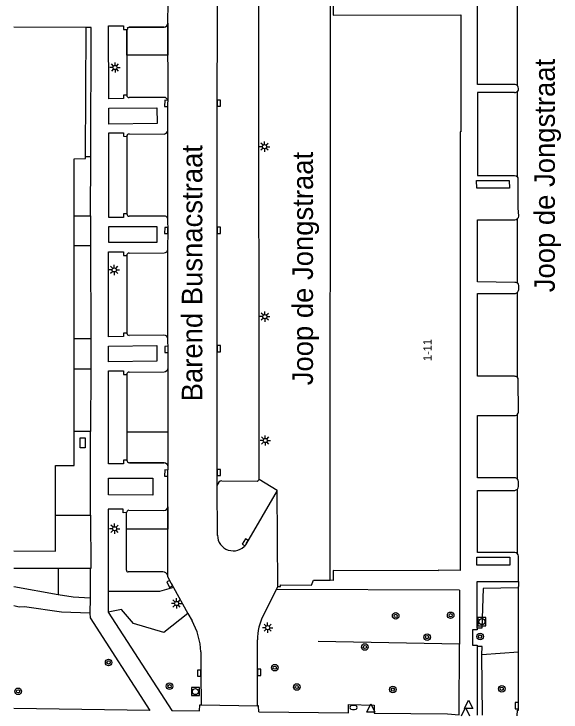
# Model space of a CAD drawing. Extents: x 132573 to 132944, y 398226 to 398676.
# Drawn here: x 132573 to 132639.7, y 398296.9 to 398381.9 of the extents above; entities that cross this region are included whole.
import ezdxf

# ---------------------------------------------------------------- set-up
doc = ezdxf.new("R2010")
doc.units = 0
for name, color, linetype in [('bp-grn-parkeervak', 7, 'Continuous'), ('gg-afsc-hekwerk', 7, 'Continuous'), ('gg-afsc-muur', 7, 'Continuous'), ('gg-anno-huisnummerreeks BGT', 7, 'Continuous'), ('gg-anno-openbare ruimte label', 7, 'Continuous'), ('gg-bbg-hoofdgebouw', 7, 'Continuous'), ('gg-knt-verharding', 7, 'Continuous'), ('gg-knt-verharding nz', 7, 'Continuous'), ('gt-grn-groengrens', 7, 'Continuous'), ('gt-grn-vlakafsluiter', 7, 'Continuous'), ('gt-symb-boom', 7, 'Continuous'), ('gt-symb-brandkraan', 7, 'Continuous'), ('gt-symb-kolk', 7, 'Continuous'), ('gt-symb-lichtmast', 7, 'Continuous'), ('gt-symb-rioolschacht', 7, 'Continuous'), ('gt-symb-waterafsluiter', 7, 'Continuous')]:
    doc.layers.add(name, color=color, linetype=linetype)

msp = doc.modelspace()

# ---------------------------------------------------------------- linework, layer by layer
at = {"layer": 'bp-grn-parkeervak'}
for p, q in [((132587.078, 398327.266), (132591.316, 398327.248)), ((132587.014, 398321.464), (132591.292, 398321.445))]:
    msp.add_line(p, q, dxfattribs=at)
for points in [[(132591.774, 398380.797), (132591.78, 398376.895), (132586.771, 398376.895), (132586.761, 398380.023)], [(132591.312, 398380.323), (132587.071, 398380.328), (132586.855, 398380.239)], [(132591.798, 398326.771), (132591.799, 398330.992), (132586.775, 398330.987), (132586.778, 398327.56)], [(132591.762, 398321.878), (132591.758, 398319.153), (132586.742, 398319.161), (132586.752, 398321.184)]]:
    msp.add_lwpolyline(points, dxfattribs=at)
for centre, radius, start, end in [((132591.29, 398380.807), 0.484, 272.60423, 358.86482), ((132586.766, 398380.149), 0.126, 267.76694, 45.19713), ((132587.103, 398327.592), 0.327, 185.59938, 265.55807), ((132591.277, 398326.727), 0.523, 4.87648, 85.72097), ((132587.037, 398321.18), 0.285, 94.57153, 179.2327), ((132591.283, 398321.926), 0.481, 271.05126, 354.25603)]:
    msp.add_arc(centre, radius, start, end, dxfattribs=at)
at = {"layer": 'gg-afsc-hekwerk'}
msp.add_line((132627.306, 398305.146), (132610.076, 398305.499), dxfattribs=at)
at = {"layer": 'gg-afsc-muur'}
for p, q in [((132582.398, 398364.533), (132581.737, 398364.536)), ((132582.362, 398357.351), (132582.398, 398364.533)), ((132580.365, 398357.35), (132582.362, 398357.351)), ((132580.363, 398353.723), (132582.357, 398353.724)), ((132582.357, 398353.724), (132582.371, 398342.349)), ((132582.371, 398342.349), (132580.355, 398342.351)), ((132580.353, 398338.703), (132582.375, 398338.705)), ((132582.375, 398338.705), (132582.362, 398331.08)), ((132582.362, 398331.08), (132580.348, 398331.081)), ((132578.093, 398320.891), (132582.363, 398320.888)), ((132578.389, 398314.392), (132573.021, 398314.394)), ((132582.303, 398314.391), (132578.389, 398314.392))]:
    msp.add_line(p, q, dxfattribs=at)
msp.add_lwpolyline([(132582.363, 398320.888), (132582.372, 398314.382), (132582.303, 398314.391)], dxfattribs=at)
at = {"layer": 'gg-bbg-hoofdgebouw'}
for p, q in [((132611.557, 398312.941), (132611.606, 398383.108)), ((132581.798, 398380.279), (132573.021, 398380.302)), ((132581.737, 398364.536), (132581.798, 398380.279)), ((132580.363, 398353.723), (132580.365, 398357.35)), ((132580.355, 398342.351), (132580.363, 398353.723)), ((132580.353, 398338.703), (132580.355, 398342.351)), ((132580.348, 398331.081), (132580.353, 398338.703))]:
    msp.add_line(p, q, dxfattribs=at)
for points in [[(132611.918, 398383.098), (132611.926, 398381.783), (132627.465, 398381.808), (132627.459, 398367.583), (132627.387, 398367.583), (132627.398, 398314.148)], [(132580.365, 398357.35), (132580.37, 398364.296), (132581.736, 398364.312), (132581.737, 398364.536)], [(132578.093, 398320.891), (132578.091, 398326.918), (132580.345, 398326.927), (132580.348, 398331.081)], [(132573.021, 398316.523), (132578.094, 398316.502), (132578.093, 398320.891)], [(132627.398, 398314.148), (132624.725, 398314.174), (132624.721, 398314.097), (132611.91, 398314.13), (132611.919, 398312.93), (132611.557, 398312.941)]]:
    msp.add_lwpolyline(points, dxfattribs=at)
at = {"layer": 'gg-knt-verharding'}
for p, q in [((132602.886, 398325.225), (132602.874, 398390.164)), ((132591.774, 398380.797), (132591.822, 398383.309)), ((132634.355, 398373.168), (132634.362, 398383.497)), ((132582.439, 398380.277), (132581.798, 398380.279)), ((132582.398, 398364.533), (132582.439, 398380.277)), ((132586.761, 398380.023), (132586.768, 398372.038)), ((132634.351, 398362.103), (132634.365, 398372.512)), ((132591.286, 398371.767), (132587.051, 398371.746)), ((132586.767, 398367.018), (132586.764, 398357.56)), ((132587.066, 398367.32), (132591.307, 398367.294)), ((132582.362, 398357.351), (132582.357, 398353.724)), ((132591.284, 398357.303), (132587.07, 398357.276)), ((132634.357, 398349.129), (132634.37, 398357.003)), ((132587.06, 398352.807), (132591.304, 398352.825)), ((132586.764, 398352.507), (132586.763, 398343.037)), ((132634.351, 398337.642), (132634.372, 398348.04)), ((132582.371, 398342.349), (132582.375, 398338.705)), ((132591.29, 398342.8), (132587.065, 398342.761)), ((132587.055, 398338.306), (132591.32, 398338.337)), ((132586.769, 398337.993), (132586.778, 398327.56)), ((132634.367, 398325.261), (132634.381, 398333.155)), ((132582.363, 398320.888), (132582.362, 398331.08)), ((132591.316, 398327.248), (132587.078, 398327.266)), ((132597.818, 398318.415), (132597.785, 398324.487)), ((132598.356, 398325.052), (132602.634, 398325.026)), ((132634.374, 398316.167), (132634.351, 398324.046)), ((132586.718, 398314.164), (132586.752, 398321.184)), ((132587.014, 398321.464), (132591.292, 398321.445)), ((132582.303, 398314.391), (132582.287, 398310.746)), ((132591.15, 398313.973), (132586.931, 398313.97)), ((132592.179, 398312.588), (132592.472, 398312.06)), ((132634.497, 398312.805), (132634.496, 398312.189)), ((132578.413, 398311.185), (132573.021, 398312.134)), ((132592.472, 398312.06), (132594.22, 398308.911)), ((132603.405, 398308.699), (132604.996, 398311.826)), ((132604.996, 398311.826), (132605.181, 398312.174)), ((132627.3, 398311.718), (132604.996, 398311.826)), ((132627.3, 398311.718), (132627.306, 398305.146)), ((132629.461, 398307.114), (132629.455, 398312.182)), ((132634.494, 398304.203), (132634.496, 398312.011)), ((132634.496, 398312.011), (132634.496, 398312.189)), ((132584.512, 398311.559), (132584.513, 398309.043)), ((132582.287, 398310.746), (132582.274, 398308.95)), ((132584.513, 398309.043), (132592.259, 398297.07)), ((132594.22, 398308.911), (132594.727, 398307.998)), ((132602.678, 398305.651), (132602.678, 398305.668)), ((132627.276, 398296.559), (132627.306, 398305.146)), ((132629.446, 398304.885), (132629.462, 398296.509)), ((132589.589, 398297.093), (132573.021, 398297.328)), ((132595.812, 398297.788), (132602.674, 398297.644)), ((132592.259, 398297.07), (132595.639, 398297.036))]:
    msp.add_line(p, q, dxfattribs=at)
for points in [[(132634.001, 398373.324), (132629.494, 398373.344), (132629.497, 398383.328), (132634.028, 398383.333), (132634.212, 398383.38), (132634.362, 398383.497)], [(132586.768, 398372.038), (132586.347, 398372.028), (132586.347, 398371.614), (132584.582, 398371.581), (132584.558, 398380.46)], [(132584.558, 398380.46), (132586.347, 398380.46), (132586.357, 398380.037), (132586.761, 398380.023)], [(132586.855, 398380.239), (132587.071, 398380.328), (132591.312, 398380.323)], [(132634.355, 398373.168), (132634.43, 398373.042), (132634.468, 398372.795), (132634.44, 398372.645), (132634.365, 398372.512)], [(132634.008, 398372.344), (132629.482, 398372.341), (132629.493, 398362.267), (132634.019, 398362.261), (132634.201, 398362.216), (132634.351, 398362.103)], [(132591.778, 398367.767), (132591.782, 398371.026), (132591.79, 398371.329)], [(132584.574, 398370.444), (132590.441, 398370.502), (132590.462, 398368.568), (132584.594, 398368.509), (132584.574, 398370.444)], [(132586.764, 398357.56), (132586.348, 398357.563), (132586.354, 398357.135), (132584.575, 398357.118), (132584.578, 398367.461), (132586.353, 398367.443), (132586.352, 398367.028), (132586.767, 398367.018)], [(132634.37, 398357.003), (132634.476, 398357.136), (132634.544, 398357.292), (132634.456, 398358.312), (132634.452, 398360.324), (132634.467, 398361.824), (132634.432, 398361.973), (132634.351, 398362.103)], [(132591.781, 398353.29), (132591.793, 398355.531), (132591.787, 398356.831)], [(132634.03, 398349.226), (132629.513, 398349.292), (132629.484, 398356.848), (132634.033, 398356.837), (132634.214, 398356.895), (132634.37, 398357.003)], [(132590.445, 398356.028), (132590.435, 398354.078), (132584.573, 398354.067), (132584.583, 398356.018), (132590.445, 398356.028)], [(132586.763, 398343.037), (132586.362, 398343.039), (132586.376, 398342.63), (132584.554, 398342.583), (132584.545, 398352.949), (132586.35, 398352.938), (132586.349, 398352.51), (132586.764, 398352.507)], [(132634.357, 398349.129), (132634.446, 398348.998), (132634.474, 398348.842), (132634.473, 398348.338), (132634.45, 398348.18), (132634.372, 398348.04)], [(132634.009, 398337.793), (132629.493, 398337.804), (132629.501, 398347.893), (132634.034, 398347.882)], [(132591.8, 398338.808), (132591.81, 398341.064), (132591.786, 398342.356)], [(132590.421, 398341.524), (132590.408, 398339.62), (132584.527, 398339.556), (132584.541, 398341.459), (132590.421, 398341.524)], [(132586.778, 398327.56), (132586.365, 398327.558), (132586.367, 398327.126), (132584.539, 398327.117), (132584.549, 398338.436), (132586.355, 398338.469), (132586.369, 398338.012), (132586.769, 398337.993)], [(132634.381, 398333.155), (132634.452, 398333.285), (132634.475, 398333.431), (132634.469, 398337.353), (132634.436, 398337.508), (132634.351, 398337.642)], [(132634.022, 398325.413), (132629.508, 398325.43), (132629.509, 398332.995), (132634.039, 398332.993)], [(132591.762, 398321.878), (132591.773, 398325.987), (132591.798, 398326.771)], [(132589.947, 398323.316), (132584.523, 398323.337), (132584.534, 398325.389), (132589.959, 398325.368), (132589.947, 398323.316)], [(132634.351, 398324.046), (132634.44, 398324.186), (132634.477, 398324.348), (132634.475, 398324.966), (132634.448, 398325.124), (132634.367, 398325.261)], [(132605.083, 398323.893), (132601.371, 398317.481), (132601.259, 398317.265)], [(132634.374, 398316.167), (132634.222, 398316.286), (132634.035, 398316.336), (132629.51, 398316.335), (132629.511, 398323.887), (132634.027, 398323.893), (132634.204, 398323.938), (132634.351, 398324.046)], [(132586.752, 398321.184), (132586.34, 398321.163), (132586.339, 398321.598), (132584.508, 398321.613), (132584.512, 398311.559)], [(132634.497, 398312.805), (132634.486, 398315.885), (132634.453, 398316.035), (132634.374, 398316.167)], [(132592.179, 398312.588), (132591.756, 398313.368), (132591.749, 398313.466)], [(132629.455, 398312.182), (132629.455, 398312.807), (132634.497, 398312.805)], [(132582.287, 398310.746), (132580.232, 398310.865), (132578.413, 398311.185)], [(132582.274, 398308.95), (132578.802, 398309.064), (132574.303, 398309.686), (132573.669, 398309.674), (132573.021, 398309.813)], [(132582.274, 398308.95), (132582.294, 398308.375), (132589.589, 398297.093)], [(132629.461, 398307.114), (132629.462, 398306.896), (132628.872, 398306.896), (132628.87, 398305.054), (132629.446, 398305.036), (132629.446, 398304.885)], [(132602.674, 398297.644), (132602.696, 398301.73), (132602.678, 398305.651)], [(132595.804, 398304.223), (132595.796, 398301.617), (132595.812, 398297.788)], [(132634.339, 398296.427), (132634.357, 398297.106), (132634.5, 398297.123), (132634.494, 398304.203)], [(132595.639, 398297.036), (132595.656, 398297.769), (132595.812, 398297.788)], [(132602.844, 398296.935), (132602.819, 398297.628), (132602.674, 398297.644)], [(132602.844, 398296.935), (132613.776, 398296.784), (132613.762, 398297.795), (132616.926, 398297.724), (132616.905, 398296.758), (132625.831, 398296.661), (132627.276, 398296.559)]]:
    msp.add_lwpolyline(points, dxfattribs=at)
for centre, radius, start, end in [((132591.29, 398380.807), 0.484, 272.60423, 358.86482), ((132586.766, 398380.149), 0.126, 267.76694, 45.19713), ((132634.019, 398372.884), 0.44, 40.14956, 92.28638), ((132634.008, 398372.808), 0.464, 270.01582, 320.38642), ((132587.047, 398372.025), 0.279, 177.2869, 270.91963), ((132591.286, 398371.258), 0.509, 8.06299, 89.95262), ((132587.061, 398367.026), 0.294, 88.98256, 181.58943), ((132591.243, 398367.828), 0.538, 276.79882, 353.44395), ((132587.07, 398357.583), 0.307, 184.23098, 270.03995), ((132591.313, 398356.83), 0.474, 0.11952, 93.52268), ((132587.072, 398352.499), 0.308, 92.18331, 178.58575), ((132591.269, 398353.338), 0.515, 273.93378, 354.60654), ((132634.099, 398348.858), 0.374, 46.35321, 100.60228), ((132634.037, 398348.317), 0.435, 269.65074, 320.45726), ((132587.083, 398343.084), 0.323, 188.30378, 266.84738), ((132591.311, 398342.325), 0.476, 3.7544, 92.57825), ((132587.069, 398338.006), 0.301, 92.71644, 182.4453), ((132591.291, 398338.847), 0.511, 273.29309, 355.62248), ((132634.011, 398337.335), 0.458, 42.10694, 90.24818), ((132634.046, 398333.419), 0.426, 269.00165, 321.6907), ((132587.103, 398327.592), 0.327, 185.59938, 265.55807), ((132591.277, 398326.727), 0.523, 4.87648, 85.72097), ((132634.036, 398324.976), 0.437, 40.66934, 91.77603), ((132598.402, 398324.434), 0.62, 94.29085, 175.10392), ((132602.534, 398325.411), 0.398, 284.51204, 332.08303), ((132587.037, 398321.18), 0.285, 94.57153, 179.2327), ((132591.283, 398321.926), 0.481, 271.05126, 354.25603), ((132599.741, 398318.445), 1.923, 180.88243, 322.15778), ((132586.917, 398314.168), 0.199, 181.20831, 274.13729), ((132591.156, 398313.373), 0.6, 8.89501, 90.61512), ((132609.388, 398305.661), 6.71, 153.08242, 179.94185), ((132587.014, 398303.756), 8.802, 3.03877, 28.80792)]:
    msp.add_arc(centre, radius, start, end, dxfattribs=at)
at = {"layer": 'gg-knt-verharding nz'}
for p, q in [((132591.79, 398371.329), (132591.774, 398380.797)), ((132591.787, 398356.831), (132591.778, 398367.767)), ((132591.786, 398342.356), (132591.781, 398353.29)), ((132591.798, 398326.771), (132591.8, 398338.808)), ((132591.749, 398313.466), (132591.762, 398321.878))]:
    msp.add_line(p, q, dxfattribs=at)
for points in [[(132597.785, 398324.487), (132597.792, 398326.07), (132597.768, 398341.148), (132597.78, 398355.563), (132597.776, 398371.059), (132597.845, 398390.796)], [(132629.359, 398361.652), (132633.344, 398361.654), (132633.413, 398360.695), (132629.428, 398360.693), (132629.359, 398361.652)], [(132581.082, 398330.309), (132581.712, 398330.309), (132581.712, 398329.059), (132581.082, 398329.059), (132581.082, 398330.309)], [(132633.416, 398315.774), (132633.418, 398314.8), (132629.423, 398314.779), (132629.421, 398315.753), (132633.416, 398315.774)], [(132605.181, 398312.174), (132605.496, 398312.185), (132605.501, 398312.391), (132609.26, 398312.363), (132609.529, 398312.948), (132611.557, 398312.941)]]:
    msp.add_lwpolyline(points, dxfattribs=at)
at = {"layer": 'gt-grn-groengrens'}
for p, q in [((132578.389, 398314.392), (132578.413, 398311.185)), ((132634.494, 398304.203), (132630.013, 398303.843)), ((132630.121, 398296.496), (132630.013, 398303.843))]:
    msp.add_line(p, q, dxfattribs=at)
for points in [[(132592.472, 398312.06), (132590.736, 398311.562), (132584.512, 398311.559)], [(132634.496, 398312.011), (132630.186, 398311.924), (132630.039, 398307.114), (132629.461, 398307.114)], [(132594.22, 398308.911), (132591.295, 398306.583), (132587.603, 398307.665), (132586.125, 398309.361), (132584.513, 398309.043)], [(132630.013, 398303.843), (132630.073, 398304.886), (132629.446, 398304.885)]]:
    msp.add_lwpolyline(points, dxfattribs=at)
at = {"layer": 'gt-grn-vlakafsluiter'}
for p, q in [((132605.083, 398323.893), (132602.886, 398325.225)), ((132605.181, 398312.174), (132605.083, 398323.893))]:
    msp.add_line(p, q, dxfattribs=at)
at = {"layer": 'gt-symb-boom'}
for centre, radius in [((132619.527, 398308.607), 0.4), ((132619.527, 398308.607), 0.2), ((132626.225, 398308.674), 0.4), ((132626.225, 398308.674), 0.2), ((132623.362, 398306.02), 0.4), ((132623.362, 398306.02), 0.2), ((132629.812, 398306.082), 0.4), ((132629.812, 398306.082), 0.2), ((132615.778, 398304.811), 0.4), ((132615.778, 398304.811), 0.2), ((132584.554, 398302.934), 0.4), ((132584.554, 398302.934), 0.2), ((132604.791, 398302.294), 0.4), ((132604.791, 398302.294), 0.2), ((132573.52, 398299.415), 0.4), ((132591.976, 398300.032), 0.4), ((132591.976, 398300.032), 0.2), ((132607.476, 398299.939), 0.4), ((132607.476, 398299.939), 0.2), ((132619.181, 398299.634), 0.4), ((132619.181, 398299.634), 0.2), ((132632.459, 398299.722), 0.4), ((132632.459, 398299.722), 0.2), ((132573.52, 398299.415), 0.2)]:
    msp.add_circle(centre, radius, dxfattribs=at)
at = {"layer": 'gt-symb-brandkraan'}
for centre, radius, start, end in [((132614.144, 398297.445), 0.206, 107.83324, 252.69938), ((132615, 398294.785), 3, 107.15835, 107.83324), ((132614.975, 398300.113), 3, 252.69938, 253.37427), ((132614.391, 398296.755), 0.938, 73.37429, 107.15835), ((132614.385, 398298.137), 0.938, 253.37427, 287.15837), ((132613.801, 398294.779), 3, 72.69939, 73.37429), ((132613.776, 398300.107), 3, 287.15837, 287.83325), ((132614.632, 398297.447), 0.206, 287.83325, 72.69939)]:
    msp.add_arc(centre, radius, start, end, dxfattribs=at)
at = {"layer": 'gt-symb-kolk'}
for points in [[(132591.782, 398371.026), (132591.792, 398371.401), (132591.392, 398371.412), (132591.372, 398370.662), (132591.772, 398370.651), (132591.782, 398371.026)], [(132597.776, 398371.059), (132597.776, 398370.684), (132598.176, 398370.684), (132598.176, 398371.434), (132597.776, 398371.434), (132597.776, 398371.059)], [(132591.783, 398355.541), (132591.787, 398355.916), (132591.387, 398355.92), (132591.379, 398355.17), (132591.779, 398355.166), (132591.783, 398355.541)], [(132597.78, 398355.563), (132597.78, 398355.188), (132598.18, 398355.188), (132598.18, 398355.938), (132597.78, 398355.938), (132597.78, 398355.563)], [(132597.768, 398341.148), (132597.769, 398340.773), (132598.169, 398340.774), (132598.167, 398341.524), (132597.767, 398341.523), (132597.768, 398341.148)], [(132591.81, 398341.064), (132591.803, 398341.439), (132591.403, 398341.432), (132591.417, 398340.682), (132591.817, 398340.689), (132591.81, 398341.064)], [(132591.773, 398325.987), (132591.785, 398326.362), (132591.385, 398326.374), (132591.362, 398325.625), (132591.761, 398325.612), (132591.773, 398325.987)], [(132597.792, 398326.07), (132597.79, 398325.695), (132598.19, 398325.693), (132598.194, 398326.443), (132597.794, 398326.445), (132597.792, 398326.07)], [(132601.371, 398317.481), (132601.559, 398317.806), (132601.213, 398318.006), (132600.837, 398317.357), (132601.183, 398317.156), (132601.371, 398317.481)], [(132592.179, 398312.588), (132592.014, 398312.925), (132591.655, 398312.749), (132591.985, 398312.075), (132592.344, 398312.251), (132592.179, 398312.588)], [(132595.796, 398301.617), (132595.797, 398301.992), (132595.397, 398301.993), (132595.395, 398301.243), (132595.795, 398301.242), (132595.796, 398301.617)], [(132602.696, 398301.73), (132602.694, 398301.355), (132603.094, 398301.353), (132603.098, 398302.103), (132602.698, 398302.105), (132602.696, 398301.73)], [(132634.495, 398297.672), (132634.495, 398298.047), (132634.095, 398298.047), (132634.095, 398297.297), (132634.495, 398297.297), (132634.495, 398297.672)]]:
    msp.add_lwpolyline(points, dxfattribs=at)
at = {"layer": 'gt-symb-lichtmast'}
for p, q in [((132585.155, 398375.585), (132584.89, 398375.85)), ((132585.332, 398375.658), (132585.332, 398376.033)), ((132585.509, 398375.585), (132585.774, 398375.85)), ((132585.082, 398375.408), (132584.707, 398375.408)), ((132585.155, 398375.231), (132584.89, 398374.966)), ((132585.332, 398375.158), (132585.332, 398374.783)), ((132585.774, 398374.966), (132585.509, 398375.231)), ((132585.582, 398375.408), (132585.957, 398375.408)), ((132603.374, 398365.933), (132603.109, 398366.198)), ((132603.551, 398366.006), (132603.551, 398366.381)), ((132603.728, 398365.933), (132603.993, 398366.198)), ((132603.301, 398365.756), (132602.926, 398365.756)), ((132603.374, 398365.579), (132603.109, 398365.314)), ((132603.551, 398365.506), (132603.551, 398365.131)), ((132603.993, 398365.314), (132603.728, 398365.579)), ((132603.801, 398365.756), (132604.176, 398365.756)), ((132585.059, 398350.923), (132584.794, 398351.188)), ((132585.236, 398350.996), (132585.236, 398351.371)), ((132585.413, 398350.923), (132585.678, 398351.188)), ((132584.986, 398350.746), (132584.611, 398350.746)), ((132585.059, 398350.569), (132584.794, 398350.304)), ((132585.236, 398350.496), (132585.236, 398350.121)), ((132585.678, 398350.304), (132585.413, 398350.569)), ((132585.486, 398350.746), (132585.861, 398350.746)), ((132603.337, 398345.054), (132602.962, 398345.054)), ((132603.41, 398345.231), (132603.145, 398345.496)), ((132603.41, 398344.877), (132603.145, 398344.612)), ((132603.587, 398345.304), (132603.587, 398345.679)), ((132603.764, 398345.231), (132604.029, 398345.496)), ((132604.029, 398344.612), (132603.764, 398344.877)), ((132603.837, 398345.054), (132604.212, 398345.054)), ((132603.587, 398344.804), (132603.587, 398344.429)), ((132603.461, 398330.14), (132603.196, 398330.405)), ((132603.638, 398330.213), (132603.638, 398330.588)), ((132603.815, 398330.14), (132604.08, 398330.405)), ((132603.388, 398329.963), (132603.013, 398329.963)), ((132603.461, 398329.786), (132603.196, 398329.521)), ((132603.638, 398329.713), (132603.638, 398329.338)), ((132604.08, 398329.521), (132603.815, 398329.786)), ((132603.888, 398329.963), (132604.263, 398329.963)), ((132585.107, 398319.395), (132584.842, 398319.66)), ((132585.284, 398319.468), (132585.284, 398319.843)), ((132585.461, 398319.395), (132585.726, 398319.66)), ((132585.034, 398319.218), (132584.659, 398319.218)), ((132585.107, 398319.041), (132584.842, 398318.776)), ((132585.284, 398318.968), (132585.284, 398318.593)), ((132585.726, 398318.776), (132585.461, 398319.041)), ((132585.534, 398319.218), (132585.909, 398319.218)), ((132592.585, 398310.117), (132592.21, 398310.117)), ((132592.658, 398310.294), (132592.393, 398310.559)), ((132592.835, 398310.367), (132592.835, 398310.742)), ((132593.012, 398310.294), (132593.277, 398310.559)), ((132593.085, 398310.117), (132593.46, 398310.117)), ((132592.658, 398309.94), (132592.393, 398309.675)), ((132592.835, 398309.867), (132592.835, 398309.492)), ((132593.277, 398309.675), (132593.012, 398309.94)), ((132603.754, 398307.342), (132603.489, 398307.607)), ((132603.931, 398307.415), (132603.931, 398307.79)), ((132604.108, 398307.342), (132604.373, 398307.607)), ((132603.681, 398307.165), (132603.306, 398307.165)), ((132603.754, 398306.988), (132603.489, 398306.723)), ((132603.931, 398306.915), (132603.931, 398306.54)), ((132604.373, 398306.723), (132604.108, 398306.988)), ((132604.181, 398307.165), (132604.556, 398307.165))]:
    msp.add_line(p, q, dxfattribs=at)
for centre in [(132585.332, 398375.408), (132603.551, 398365.756), (132585.236, 398350.746), (132603.587, 398345.054), (132603.638, 398329.963), (132585.284, 398319.218), (132592.835, 398310.117), (132603.931, 398307.165)]:
    msp.add_circle(centre, 0.25, dxfattribs=at)
at = {"layer": 'gt-symb-rioolschacht'}
for points in [[(132629.528, 398307.404), (132630.528, 398307.404), (132630.528, 398308.404), (132629.528, 398308.404)], [(132594.634, 398298.885), (132595.634, 398298.885), (132595.634, 398299.885), (132594.634, 398299.885)]]:
    msp.add_lwpolyline(points, close=True, dxfattribs=at)
for centre in [(132630.028, 398307.904), (132595.134, 398299.385)]:
    msp.add_circle(centre, 0.375, dxfattribs=at)
at = {"layer": 'gt-symb-waterafsluiter'}
for p, q in [((132627.915, 398297.34), (132628.415, 398298.34)), ((132628.415, 398298.34), (132628.915, 398297.34)), ((132615.995, 398296.893), (132616.495, 398297.893)), ((132616.495, 398297.893), (132616.995, 398296.893)), ((132627.534, 398296.44), (132628.034, 398297.44)), ((132628.915, 398297.34), (132627.915, 398297.34)), ((132628.034, 398297.44), (132628.534, 398296.44)), ((132616.995, 398296.893), (132615.995, 398296.893))]:
    msp.add_line(p, q, dxfattribs=at)

# ---------------------------------------------------------------- texts
at = {"layer": 'gg-anno-huisnummerreeks BGT'}
msp.add_text('1-11', height=1, rotation=90, dxfattribs=at).set_placement((132623.893, 398339.648))
at = {"layer": 'gg-anno-openbare ruimte label'}
for s, p in [('Joop de Jongstraat', (132638.92, 398348.026)), ('Barend Busnacstraat', (132595.968, 398334.738)), ('Joop de Jongstraat', (132609.45, 398336.691))]:
    msp.add_text(s, height=2.5, rotation=90, dxfattribs=at).set_placement(p)

doc.saveas('drawing.dxf')
